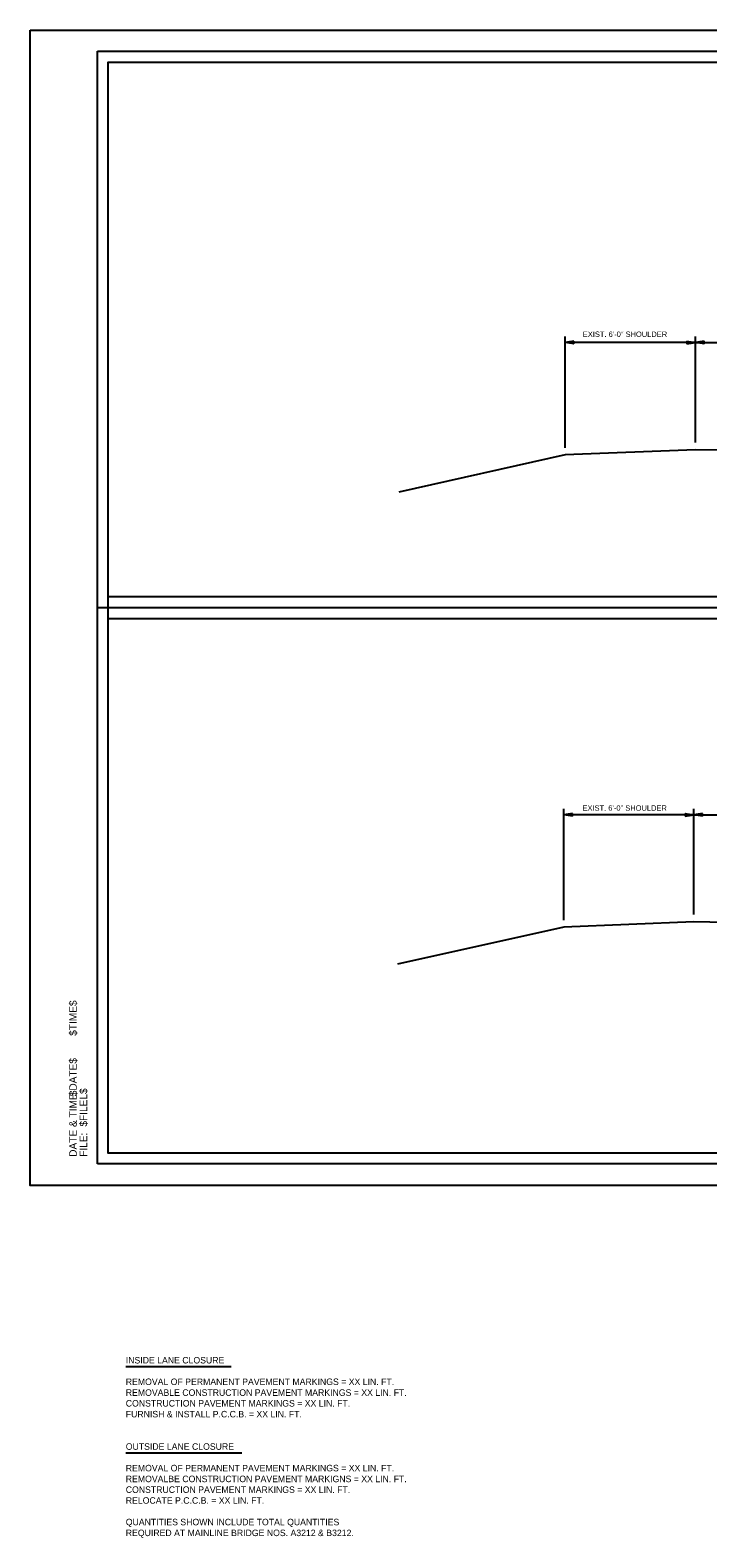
# Model space of a CAD drawing. Extents: x 13528 to 25043, y 7635 to 10612.
# Drawn here: x 19729 to 20354, y 9220 to 10612 of the extents above; entities that cross this region are included whole.
import ezdxf

# ---------------------------------------------------------------- set-up
doc = ezdxf.new("R2010")
doc.units = 0
for name, color, linetype in [('Default', 7, 'Continuous'), ('R_Border Notes', 7, 'Continuous'), ('R_Border Plan-Plan', 7, 'Continuous'), ('R_Draft', 7, 'Continuous'), ('R_Revision Date Text', 7, 'Continuous')]:
    doc.layers.add(name, color=color, linetype=linetype)

msp = doc.modelspace()

# ---------------------------------------------------------------- linework, layer by layer
at = {"layer": 'Default'}
for p, q in [((20222.7, 10295), (20222.7, 10328.6)), ((20342.8, 10230.9), (20342.8, 10328.6)), ((20230.7, 10324.3), (20222.7, 10323.1)), ((20342.8, 10323.1), (20222.7, 10323.1)), ((20230.7, 10321.9), (20222.7, 10323.1)), ((20230.7, 10324.1), (20224.1, 10323.1)), ((20230.7, 10322.1), (20224.1, 10323.1)), ((20230.7, 10323.9), (20225.5, 10323.1)), ((20230.7, 10322.3), (20225.5, 10323.1)), ((20230.7, 10323.7), (20226.8, 10323.1)), ((20230.7, 10322.5), (20226.8, 10323.1)), ((20230.7, 10323.5), (20228.1, 10323.1)), ((20230.7, 10322.7), (20228.1, 10323.1)), ((20230.7, 10323.3), (20229.5, 10323.1)), ((20230.7, 10322.9), (20229.5, 10323.1)), ((20230.7, 10321.9), (20230.7, 10324.3)), ((20334.8, 10324.3), (20342.8, 10323.1)), ((20334.8, 10324.3), (20334.8, 10321.9)), ((20334.8, 10324.1), (20341.4, 10323.1)), ((20334.8, 10323.9), (20340, 10323.1)), ((20334.8, 10323.7), (20338.7, 10323.1)), ((20334.8, 10323.5), (20337.4, 10323.1)), ((20334.8, 10323.3), (20336, 10323.1)), ((20334.8, 10321.9), (20342.8, 10323.1)), ((20334.8, 10322.7), (20337.4, 10323.1)), ((20334.8, 10322.3), (20340, 10323.1)), ((20334.8, 10322.1), (20341.4, 10323.1)), ((20334.8, 10322.5), (20338.7, 10323.1)), ((20334.8, 10322.9), (20336, 10323.1)), ((20350.8, 10324.3), (20342.8, 10323.1)), ((20342.8, 10323.1), (20582.8, 10323.1)), ((20350.8, 10321.9), (20342.8, 10323.1)), ((20350.8, 10324.1), (20344.1, 10323.1)), ((20350.8, 10322.1), (20344.1, 10323.1)), ((20350.8, 10323.9), (20345.5, 10323.1)), ((20350.8, 10322.3), (20345.5, 10323.1)), ((20350.8, 10323.7), (20346.8, 10323.1)), ((20350.8, 10322.5), (20346.8, 10323.1)), ((20350.8, 10323.5), (20348.2, 10323.1)), ((20350.8, 10322.7), (20348.2, 10323.1)), ((20350.8, 10323.3), (20349.5, 10323.1)), ((20350.8, 10322.9), (20349.5, 10323.1)), ((20350.8, 10321.9), (20350.8, 10324.3)), ((20222.7, 10225.9), (20222.7, 10295)), ((20222.7, 10219.4), (20069.1, 10185)), ((20342.8, 10224.2), (20222.7, 10219.4)), ((20582.8, 10219.4), (20342.8, 10224.2)), ((20221.4, 9859.1), (20221.4, 9892.7)), ((20229.4, 9888.4), (20221.4, 9887.2)), ((20341.4, 9887.2), (20221.4, 9887.2)), ((20229.4, 9886), (20221.4, 9887.2)), ((20229.4, 9888.2), (20222.7, 9887.2)), ((20229.4, 9886.2), (20222.7, 9887.2)), ((20229.4, 9888), (20224.1, 9887.2)), ((20229.4, 9886.4), (20224.1, 9887.2)), ((20229.4, 9887.8), (20225.4, 9887.2)), ((20229.4, 9886.6), (20225.4, 9887.2)), ((20229.4, 9887.6), (20226.8, 9887.2)), ((20229.4, 9886.8), (20226.8, 9887.2)), ((20229.4, 9887.4), (20228.1, 9887.2)), ((20229.4, 9887), (20228.1, 9887.2)), ((20229.4, 9886), (20229.4, 9888.4)), ((20333.4, 9888.4), (20341.4, 9887.2)), ((20333.4, 9888.4), (20333.4, 9886)), ((20333.4, 9888.2), (20340, 9887.2)), ((20333.4, 9888), (20338.7, 9887.2)), ((20333.4, 9887.8), (20337.3, 9887.2)), ((20333.4, 9887.6), (20336, 9887.2)), ((20333.4, 9887.4), (20334.6, 9887.2)), ((20333.4, 9886), (20341.4, 9887.2)), ((20333.4, 9886.8), (20336, 9887.2)), ((20333.4, 9886.4), (20338.7, 9887.2)), ((20333.4, 9886.2), (20340, 9887.2)), ((20333.4, 9886.6), (20337.3, 9887.2)), ((20333.4, 9887), (20334.6, 9887.2)), ((20341.4, 9795), (20341.4, 9892.7)), ((20349.4, 9888.4), (20341.4, 9887.2)), ((20341.4, 9887.2), (20581.4, 9887.2)), ((20349.4, 9886), (20341.4, 9887.2)), ((20349.4, 9888.2), (20342.7, 9887.2)), ((20349.4, 9886.2), (20342.7, 9887.2)), ((20349.4, 9888), (20344.1, 9887.2)), ((20349.4, 9886.4), (20344.1, 9887.2)), ((20349.4, 9887.8), (20345.4, 9887.2)), ((20349.4, 9886.6), (20345.4, 9887.2)), ((20349.4, 9887.6), (20346.8, 9887.2)), ((20349.4, 9886.8), (20346.8, 9887.2)), ((20349.4, 9887.4), (20348.1, 9887.2)), ((20349.4, 9887), (20348.1, 9887.2)), ((20349.4, 9886), (20349.4, 9888.4)), ((20221.4, 9790), (20221.4, 9859.1)), ((20341.4, 9788.4), (20221.4, 9783.5)), ((20581.4, 9783.6), (20341.4, 9788.4)), ((20221.4, 9783.5), (20067.8, 9749.1))]:
    msp.add_line(p, q, dxfattribs=at)
at = {"layer": 'R_Border Notes'}
for p, q in [((19817.1, 9377.8), (19914.4, 9377.8)), ((19817.1, 9298.1), (19924.3, 9298.1))]:
    msp.add_line(p, q, dxfattribs=at)
at = {"layer": 'R_Border Plan-Plan'}
msp.add_line((19790.9, 10078.4), (21371.8, 10078.4), dxfattribs=at)
at = {"layer": 'R_Draft'}
for p, q in [((19790.9, 10592.1), (21371.8, 10592.1)), ((19790.9, 9564.8), (19790.9, 10592.1)), ((19790.9, 9564.8), (19790.9, 9564.8)), ((21371.8, 9564.8), (19790.9, 9564.8))]:
    msp.add_line(p, q, dxfattribs=at)
at = {"layer": 'R_Revision Date Text'}
for points in [[(19728.9, 10611.5), (21395.6, 10611.5), (21395.6, 9544.9), (19728.9, 9544.9)], [(21361.8, 10088.4), (19800.9, 10088.4), (19800.9, 10582.1), (21048.6, 10582.1), (21048.6, 10532.7), (21136.3, 10532.7), (21256.8, 10532.7), (21256.8, 10421), (21361.8, 10421)], [(19800.9, 10582.1), (21048.6, 10582.1), (21048.6, 10532.7), (21136.3, 10532.7), (21256.8, 10532.7), (21256.8, 10421), (21361.8, 10421), (21361.8, 9574.8), (19800.9, 9574.8)], [(19800.9, 10068.4), (21361.8, 10068.4), (21361.8, 9574.8), (19800.9, 9574.8)]]:
    msp.add_lwpolyline(points, close=True, dxfattribs=at)

# ---------------------------------------------------------------- texts
at = {"layer": 'Default'}
for p in [(20238.9, 10328.3), (20238.6, 9890.9)]:
    msp.add_text('EXIST. 6\'-0" SHOULDER', height=5.001, dxfattribs=at).set_placement(p)
at = {"layer": 'R_Border Notes'}
for s, height, p in [('$TIME$', 6.98, (19771.9, 9683.1)), ('$DATE$', 6.98, (19771.9, 9627.3)), ('$FILEL$', 6.98, (19781.5, 9599.3)), ('DATE & TIME:', 6.984, (19771.9, 9571.4)), ('FILE: ', 6.98, (19781.5, 9571.4))]:
    msp.add_text(s, height=height, rotation=90, dxfattribs=at).set_placement(p)
for s, p in [('INSIDE LANE CLOSURE ', (19817.1, 9380.6)), ('REMOVAL OF PERMANENT PAVEMENT MARKINGS = XX LIN. FT.', (19817.1, 9360.7)), ('REMOVABLE CONSTRUCTION PAVEMENT MARKINGS = XX LIN. FT.', (19817.1, 9350.7)), ('CONSTRUCTION PAVEMENT MARKINGS = XX LIN. FT.', (19817.1, 9340.8)), ('FURNISH & INSTALL P.C.C.B. = XX LIN. FT.', (19817.1, 9330.8)), ('OUTSIDE LANE CLOSURE', (19817.1, 9300.9)), ('REMOVAL OF PERMANENT PAVEMENT MARKINGS = XX LIN. FT.', (19817.1, 9281)), ('REMOVALBE CONSTRUCTION PAVEMENT MARKIGNS = XX LIN. FT.', (19817.1, 9271)), ('CONSTRUCTION PAVEMENT MARKINGS = XX LIN. FT.', (19817.1, 9261.1)), ('RELOCATE P.C.C.B. = XX LIN. FT.', (19817.1, 9251.1)), ('QUANTITIES SHOWN INCLUDE TOTAL QUANTITIES', (19817.1, 9231.2)), ('REQUIRED AT MAINLINE BRIDGE NOS. A3212 & B3212.', (19817.1, 9221.2))]:
    msp.add_text(s, height=6, dxfattribs=at).set_placement(p)

doc.saveas('drawing.dxf')
